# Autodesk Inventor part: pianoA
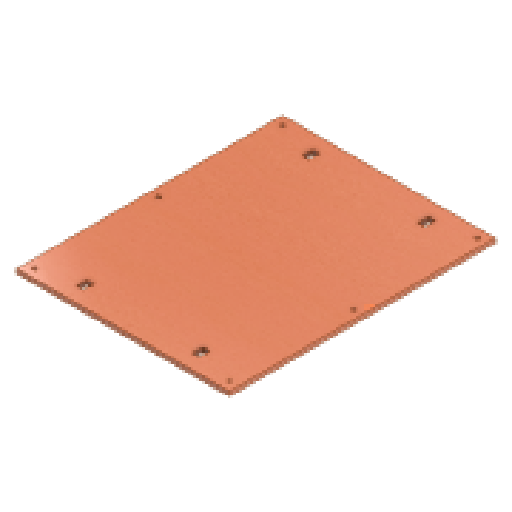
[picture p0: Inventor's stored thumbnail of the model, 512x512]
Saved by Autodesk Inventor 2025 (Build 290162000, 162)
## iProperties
Created: 2025-05
Part Number: pianoA
Material: Legno (noce)
Document SubType Name: Modeling
Designer: R5800u
Density: 0.55 g/cm^3
Appearance: Noce - Naturale lucidato
Author: R5800u
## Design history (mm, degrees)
sketch "Schizzo1"
  geometry: L1 (120, 150)-(-120, 150); L2 (-120, 150)-(-120, -150); L3 (-120, -150)-(120, -150); L4 (120, -150)-(120, 150); L5 (120, 150)-(-120, -150); L6 (-120, 150)-(120, -150); 1 further point
  constraints: 12 end point, 2 midpoint, 2 parallel, 1 horizontal, 1 perpendicular
  dimensions: "d0" = 240 distance of L3.end L2.end; "d1" = 300 distance of L2.end L1.end
extrude "Estrusione1" new body sketch "Schizzo1" distance "d2" = 5; taper "d3" = 0 deg
sketch "Schizzo2"
  geometry: L1 (-120, 150)-(120, 150) reference; L2 (-110, 150)-(-110, -150); L3 (120, -150)-(-120, -150) reference; L4 (-120, -150)-(-120, 150) reference; L5 (0, 0)-(0, 187.277) reference; L6 (110, 150)-(110, -150); L7 (120, -150)-(120, 150); C1 r 2.1 at (-110, -140) reference; 5 further points
  constraints: 8 end point, 5 point on line, 4 symmetric about line, 3 vertical, 1 midpoint
  dimensions: "d4" = 10 distance between parallel lines of L4 L2; "d5" = 10 distance from line of L1 point (-110, 140); "d14" = 10 distance from line of L3 point (110, -140)
hole "Foro1" sketch "Schizzo2" at (-110, 140), (-110, 0), (110, -140), (110, 0), (110, 140), (-110, -140) diameter "d7" = 4.5; stored, may be unused: countersink angle "d11" = 90 deg, drill point angle "d13" = 118 deg; dims "d8" = 6, "d9" = 9.4, "d10" = 2, "d12" = 8.8
sketch "Schizzo3"
  geometry: L1 (-65.5, -123.85)-(-65.5, -131.15) reference; L2 (-69.5, -121.5)-(-61.5, -121.5); L3 (-61.5, -121.5)-(-61.5, -133.5); L4 (-61.5, -133.5)-(-69.5, -133.5); L5 (-69.5, -133.5)-(-69.5, -121.5); L6 (-69.5, -121.5)-(-61.5, -133.5); L7 (-61.5, -121.5)-(-69.5, -133.5); L8 (120, -150)-(-120, -150) reference; L9 (0, -150)-(0, 150); L10 (-120, 150)-(120, 150) reference; L11 (65.5, -123.85)-(65.5, -131.15); L12 (69.5, -121.5)-(61.5, -121.5); L13 (61.5, -121.5)-(61.5, -133.5); L14 (61.5, -133.5)-(69.5, -133.5); L15 (69.5, -133.5)-(69.5, -121.5); L16 (69.5, -121.5)-(61.5, -133.5); L17 (61.5, -121.5)-(69.5, -133.5); L18 (0, 0)-(120, 0); L19 (120, 150)-(120, -150) reference; L20 (65.5, 123.85)-(65.5, 131.15); L21 (69.5, 121.5)-(61.5, 121.5); L22 (61.5, 121.5)-(61.5, 133.5); L23 (61.5, 133.5)-(69.5, 133.5); L24 (69.5, 133.5)-(69.5, 121.5); L25 (61.5, 121.5)-(69.5, 133.5); L26 (69.5, 121.5)-(61.5, 133.5); L27 (-65.5, 123.85)-(-65.5, 131.15); L28 (-61.5, 121.5)-(-61.5, 133.5); L29 (-69.5, 121.5)-(-61.5, 121.5); L30 (-61.5, 133.5)-(-69.5, 133.5); L31 (-69.5, 133.5)-(-69.5, 121.5); L32 (-69.5, 121.5)-(-61.5, 133.5); L33 (-61.5, 121.5)-(-69.5, 133.5); 4 further points
  constraints: 58 end point, 21 symmetric about line, 6 midpoint, 2 parallel, 1 horizontal, 1 perpendicular
  dimensions: "d17" = 8 distance of L3.end L4.end; "d18" = 12 distance of L2.end L3.end
extrude "Estrusione2" cut sketch "Schizzo3" extent not by distance; stored distance "d19" = 0; taper "d20" = 0 deg
node "Solido1"
node "Riferimento1"
node "Riferimento2"
